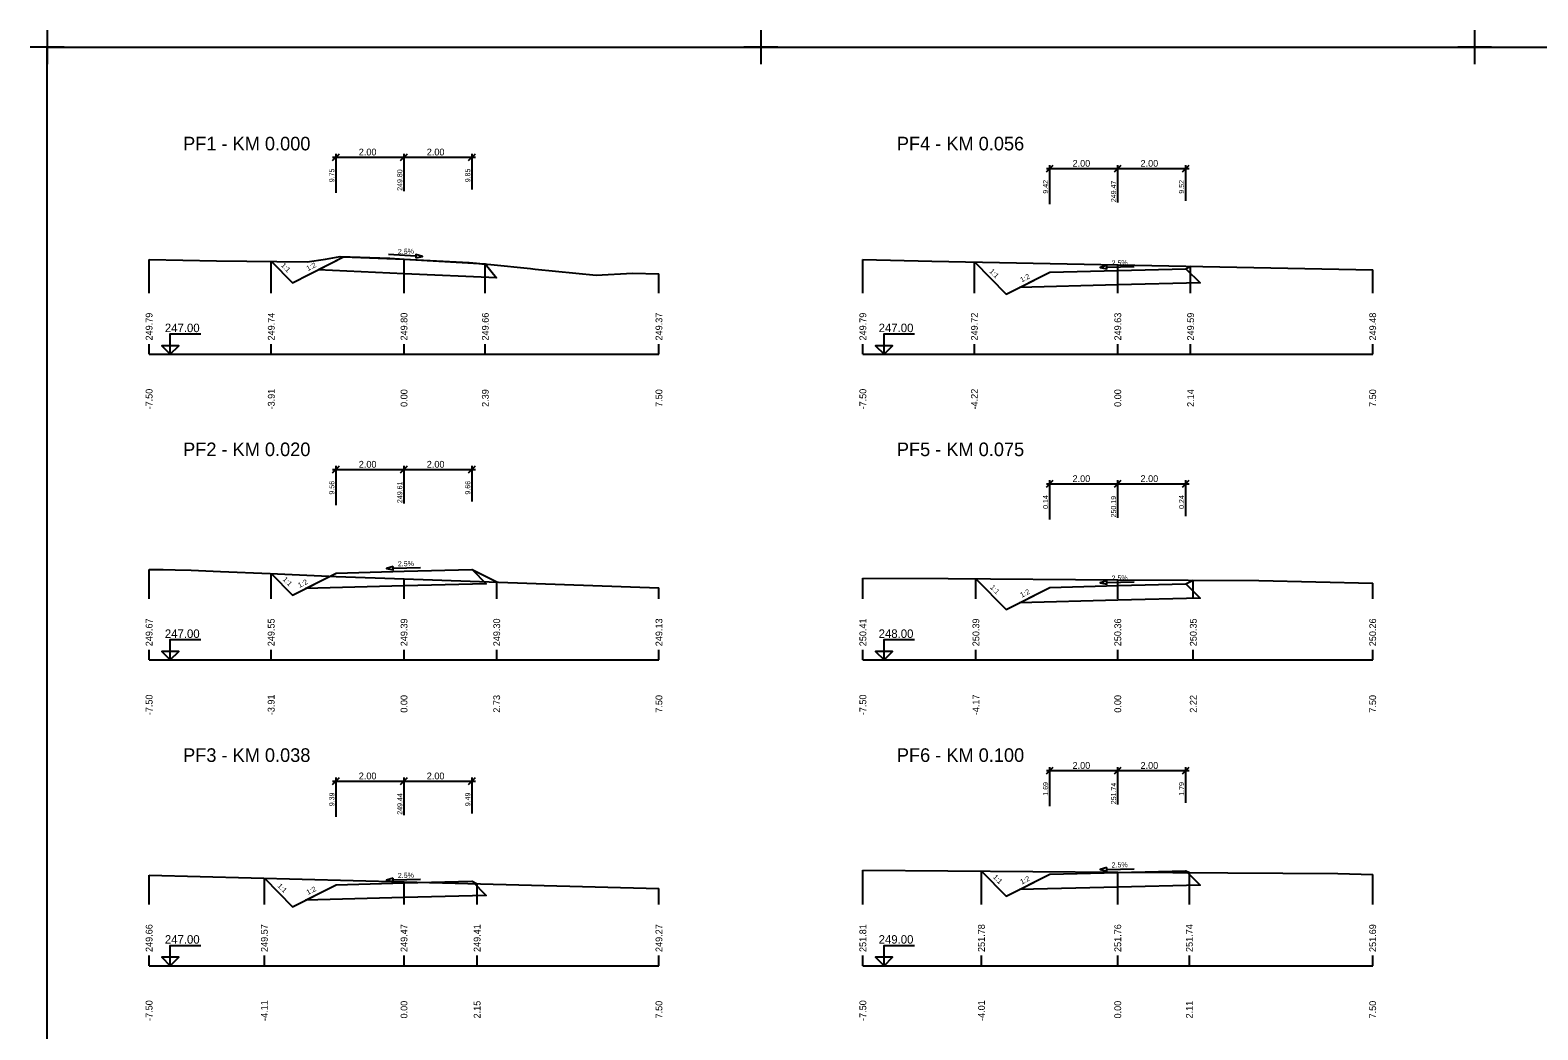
# Model space of a CAD drawing. Extents: x -5 to 1895, y -2 to 602.
# Drawn here: x -5 to 438.6, y 308.1 to 602.4 of the extents above; entities that cross this region are included whole.
import ezdxf

# ---------------------------------------------------------------- set-up
doc = ezdxf.new("R2010")
doc.units = 0
for name, color, linetype in [('KOTA', 7, 'Continuous'), ('KOTA_DELKY', 7, 'Continuous'), ('KOTA_DELKY_CONT', 7, 'Continuous'), ('NS_TELESO_VOZOVKY', 7, 'Continuous'), ('NS_V_PF', 7, 'Continuous'), ('REZY_PF_PUVODNI', 7, 'Continuous'), ('SESTAVY_REZU_PF', 7, 'Continuous'), ('SKLON', 7, 'Continuous'), ('SVK', 7, 'Continuous')]:
    doc.layers.add(name, color=color, linetype=linetype)

msp = doc.modelspace()

# ---------------------------------------------------------------- linework, layer by layer
for p, q in [((0, 602.39), (0, 592.39)), ((0, 602.39), (0, 592.39)), ((0, 602.39), (0, 592.39)), ((0, 602.39), (0, 592.39)), ((0, 602.39), (0, 592.39)), ((0, 602.39), (0, 592.39)), ((210, 602.39), (210, 592.39)), ((210, 602.39), (210, 592.39)), ((210, 602.39), (210, 592.39)), ((210, 602.39), (210, 592.39)), ((210, 602.39), (210, 592.39)), ((210, 602.39), (210, 592.39)), ((210, 602.39), (210, 592.39)), ((210, 602.39), (210, 592.39)), ((210, 602.39), (210, 592.39)), ((210, 602.39), (210, 592.39)), ((210, 602.39), (210, 592.39)), ((210, 602.39), (210, 592.39)), ((210, 602.39), (210, 592.39)), ((210, 602.39), (210, 592.39)), ((210, 602.39), (210, 592.39)), ((210, 602.39), (210, 592.39)), ((210, 602.39), (210, 592.39)), ((210, 602.39), (210, 592.39)), ((420, 602.39), (420, 592.39)), ((420, 602.39), (420, 592.39)), ((420, 602.39), (420, 592.39)), ((420, 602.39), (420, 592.39)), ((420, 602.39), (420, 592.39)), ((420, 602.39), (420, 592.39)), ((420, 602.39), (420, 592.39)), ((420, 602.39), (420, 592.39)), ((420, 602.39), (420, 592.39)), ((420, 602.39), (420, 592.39)), ((420, 602.39), (420, 592.39)), ((420, 602.39), (420, 592.39)), ((420, 602.39), (420, 592.39)), ((420, 602.39), (420, 592.39)), ((420, 602.39), (420, 592.39)), ((420, 602.39), (420, 592.39)), ((420, 602.39), (420, 592.39)), ((420, 602.39), (420, 592.39)), ((5, 597.39), (-5, 597.39)), ((5, 597.39), (-5, 597.39)), ((5, 597.39), (-5, 597.39)), ((5, 597.39), (-5, 597.39)), ((5, 597.39), (-5, 597.39)), ((5, 597.39), (-5, 597.39)), ((215, 597.39), (205, 597.39)), ((215, 597.39), (205, 597.39)), ((215, 597.39), (205, 597.39)), ((215, 597.39), (205, 597.39)), ((215, 597.39), (205, 597.39)), ((215, 597.39), (205, 597.39)), ((215, 597.39), (205, 597.39)), ((215, 597.39), (205, 597.39)), ((215, 597.39), (205, 597.39)), ((215, 597.39), (205, 597.39)), ((215, 597.39), (205, 597.39)), ((215, 597.39), (205, 597.39)), ((215, 597.39), (205, 597.39)), ((215, 597.39), (205, 597.39)), ((215, 597.39), (205, 597.39)), ((215, 597.39), (205, 597.39)), ((215, 597.39), (205, 597.39)), ((215, 597.39), (205, 597.39)), ((425, 597.39), (415, 597.39)), ((425, 597.39), (415, 597.39)), ((425, 597.39), (415, 597.39)), ((425, 597.39), (415, 597.39)), ((425, 597.39), (415, 597.39)), ((425, 597.39), (415, 597.39)), ((425, 597.39), (415, 597.39)), ((425, 597.39), (415, 597.39)), ((425, 597.39), (415, 597.39)), ((425, 597.39), (415, 597.39)), ((425, 597.39), (415, 597.39)), ((425, 597.39), (415, 597.39)), ((425, 597.39), (415, 597.39)), ((425, 597.39), (415, 597.39)), ((425, 597.39), (415, 597.39)), ((425, 597.39), (415, 597.39)), ((425, 597.39), (415, 597.39)), ((425, 597.39), (415, 597.39))]:
    msp.add_line(p, q)
msp.add_lwpolyline([(0, 597.39), (1890, 597.39), (1890, 3.39), (0, 3.39)], close=True)
at = {"layer": 'KOTA'}
for points in [[(36.22, 509.5), (33.72, 509.5), (36.22, 507), (36.22, 513), (45.22, 513)], [(246.22, 509.5), (243.72, 509.5), (246.22, 507), (246.22, 513), (255.22, 513)], [(36.22, 507), (38.72, 509.5), (36.22, 509.5)], [(246.22, 507), (248.72, 509.5), (246.22, 509.5)], [(36.22, 419.5), (33.72, 419.5), (36.22, 417), (36.22, 423), (45.22, 423)], [(246.22, 419.5), (243.72, 419.5), (246.22, 417), (246.22, 423), (255.22, 423)], [(36.22, 417), (38.72, 419.5), (36.22, 419.5)], [(246.22, 417), (248.72, 419.5), (246.22, 419.5)], [(36.22, 329.5), (33.72, 329.5), (36.22, 327), (36.22, 333), (45.22, 333)], [(246.22, 329.5), (243.72, 329.5), (246.22, 327), (246.22, 333), (255.22, 333)], [(36.22, 327), (38.72, 329.5), (36.22, 329.5)], [(246.22, 327), (248.72, 329.5), (246.22, 329.5)]]:
    msp.add_lwpolyline(points, dxfattribs=at)
at = {"layer": 'KOTA_DELKY'}
for points in [[(84, 564.01), (86, 566.01)], [(84, 565.01), (106, 565.01)], [(85, 554.51), (85, 566.01)], [(104, 564.01), (106, 566.01)], [(104, 564.01), (106, 566.01)], [(104, 565.01), (126, 565.01)], [(105, 555.01), (105, 566.01)], [(105, 555.01), (105, 566.01)], [(124, 564.01), (126, 566.01)], [(125, 555.51), (125, 566.01)], [(294, 560.68), (296, 562.68)], [(294, 561.68), (316, 561.68)], [(295, 551.18), (295, 562.68)], [(314, 560.68), (316, 562.68)], [(314, 560.68), (316, 562.68)], [(314, 561.68), (336, 561.68)], [(315, 551.68), (315, 562.68)], [(315, 551.68), (315, 562.68)], [(334, 560.68), (336, 562.68)], [(335, 552.18), (335, 562.68)], [(84, 472.1), (86, 474.1)], [(84, 473.1), (106, 473.1)], [(85, 462.6), (85, 474.1)], [(104, 472.1), (106, 474.1)], [(104, 472.1), (106, 474.1)], [(104, 473.1), (126, 473.1)], [(105, 463.1), (105, 474.1)], [(105, 463.1), (105, 474.1)], [(124, 472.1), (126, 474.1)], [(125, 463.6), (125, 474.1)], [(294, 467.88), (296, 469.88)], [(294, 468.88), (316, 468.88)], [(295, 458.38), (295, 469.88)], [(314, 467.88), (316, 469.88)], [(314, 467.88), (316, 469.88)], [(314, 468.88), (336, 468.88)], [(315, 458.88), (315, 469.88)], [(315, 458.88), (315, 469.88)], [(334, 467.88), (336, 469.88)], [(335, 459.38), (335, 469.88)], [(84, 380.36), (86, 382.36)], [(85, 370.86), (85, 382.36)], [(104, 380.36), (106, 382.36)], [(104, 380.36), (106, 382.36)], [(105, 371.36), (105, 382.36)], [(105, 371.36), (105, 382.36)], [(124, 380.36), (126, 382.36)], [(125, 371.86), (125, 382.36)], [(294, 383.45), (296, 385.45)], [(294, 384.45), (316, 384.45)], [(295, 373.95), (295, 385.45)], [(314, 383.45), (316, 385.45)], [(314, 383.45), (316, 385.45)], [(314, 384.45), (336, 384.45)], [(315, 374.45), (315, 385.45)], [(315, 374.45), (315, 385.45)], [(334, 383.45), (336, 385.45)], [(335, 374.95), (335, 385.45)], [(84, 381.36), (106, 381.36)], [(104, 381.36), (126, 381.36)]]:
    msp.add_lwpolyline(points, dxfattribs=at)
at = {"layer": 'NS_TELESO_VOZOVKY'}
for points in [[(105, 535.01), (128.89, 533.58), (128.89, 533.58), (132.21, 529.46), (105, 530.71), (79.7, 531.86), (87.2, 535.69), (87.2, 535.69), (105, 535.01)], [(315, 531.68), (335, 532.18), (335, 532.18), (339.2, 527.98), (315, 527.38), (286.05, 526.65), (295, 531.18), (295, 531.18), (315, 531.68)], [(105, 443.1), (125, 443.6), (125, 443.6), (129.2, 439.4), (105, 438.8), (76.05, 438.08), (85, 442.6), (85, 442.6), (105, 443.1)], [(315, 438.88), (335, 439.38), (335, 439.38), (339.2, 435.19), (315, 434.58), (286.05, 433.86), (295, 438.38), (295, 438.38), (315, 438.88)], [(315, 354.45), (335, 354.95), (335, 354.95), (339.2, 350.75), (315, 350.15), (286.05, 349.43), (295, 353.95), (295, 353.95), (315, 354.45)], [(105, 351.36), (125, 351.86), (125, 351.86), (129.2, 347.66), (105, 347.06), (76.05, 346.34), (85, 350.86), (85, 350.86), (105, 351.36)]]:
    msp.add_lwpolyline(points, dxfattribs=at)
at = {"layer": 'NS_V_PF'}
for points in [[(65.94, 534.35), (72.19, 528.04), (87.2, 535.69), (87.2, 535.69), (105, 535.01), (124.21, 533.97), (124.21, 533.97), (128.92, 533.55)], [(272.82, 534.17), (282.19, 524.7), (295, 531.18), (295, 531.18), (315, 531.68), (335, 532.18), (335, 532.18), (336.43, 532.89)], [(65.91, 442.46), (72.19, 436.12), (85, 442.6), (85, 442.6), (105, 443.1), (125, 443.6), (125, 443.6), (132.27, 439.96)], [(273.26, 440.93), (282.19, 431.9), (295, 438.38), (295, 438.38), (315, 438.88), (335, 439.38), (335, 439.38), (337.21, 440.49)], [(274.89, 354.84), (282.19, 347.47), (295, 353.95), (295, 353.95), (315, 354.45), (335, 354.95), (335, 354.95), (336.06, 354.42)], [(63.91, 352.75), (72.19, 344.38), (85, 350.86), (85, 350.86), (105, 351.36), (125, 351.86), (125, 351.86), (126.51, 351.11)]]:
    msp.add_lwpolyline(points, dxfattribs=at)
at = {"layer": 'REZY_PF_PUVODNI'}
for points in [[(30, 534.88), (49.84, 534.52), (76.52, 534.24), (81.87, 534.99), (86.21, 535.74), (100.87, 535.24), (105, 535.01), (124.21, 533.97), (130.52, 533.41), (142.2, 532.26), (143.63, 532.01), (161.57, 530.24), (172.23, 530.9), (180, 530.67)], [(240, 534.92), (260.27, 534.42), (315, 533.32), (390, 531.82)], [(30, 443.68), (34.16, 443.61), (37.66, 443.53), (42.36, 443.45), (50.98, 443.04), (65.65, 442.48), (85.02, 441.62), (105, 440.92), (180, 438.28)], [(240, 441.07), (265.09, 440.99), (315, 440.64), (356.49, 440.35), (390, 439.59)], [(240, 355.09), (315, 354.57), (379.76, 354.12), (390, 353.89)], [(30, 353.64), (105, 351.67), (180, 349.7)]]:
    msp.add_lwpolyline(points, dxfattribs=at)
at = {"layer": 'SESTAVY_REZU_PF'}
for points in [[(30, 507), (180, 507)], [(240, 507), (390, 507)], [(30, 417), (180, 417)], [(240, 417), (390, 417)], [(30, 327), (180, 327)], [(240, 327), (390, 327)]]:
    msp.add_lwpolyline(points, dxfattribs=at)
at = {"layer": 'SKLON'}
for points in [[(108.47, 535.84), (100.48, 536.33)], [(108.44, 535.34), (110.46, 535.72), (108.5, 536.34), (108.44, 535.34)], [(311.79, 533.1), (309.8, 532.55), (311.81, 532.1), (311.79, 533.1)], [(311.8, 532.6), (319.8, 532.8)], [(101.79, 444.52), (99.8, 443.97), (101.81, 443.52), (101.79, 444.52)], [(101.8, 444.02), (109.8, 444.22)], [(311.79, 440.3), (309.8, 439.75), (311.81, 439.3), (311.79, 440.3)], [(311.8, 439.8), (319.8, 440)], [(311.79, 355.87), (309.8, 355.32), (311.81, 354.87), (311.79, 355.87)], [(311.8, 355.37), (319.8, 355.57)], [(101.79, 352.78), (99.8, 352.23), (101.81, 351.78), (101.79, 352.78)], [(101.8, 352.28), (109.8, 352.48)]]:
    msp.add_lwpolyline(points, dxfattribs=at)
at = {"layer": 'SVK'}
for points in [[(30, 525), (30, 534.88)], [(65.94, 525), (65.94, 534.35)], [(105, 525), (105, 535.01)], [(128.92, 525), (128.92, 533.55)], [(240, 525), (240, 534.92)], [(272.82, 525), (272.82, 534.17)], [(315, 525), (315, 533.32)], [(336.43, 525), (336.43, 532.89)], [(180, 525), (180, 530.67)], [(390, 525), (390, 531.82)], [(30, 507), (30, 510)], [(65.94, 507), (65.94, 510)], [(105, 507), (105, 510)], [(128.92, 507), (128.92, 510)], [(180, 507), (180, 510)], [(240, 507), (240, 510)], [(272.82, 507), (272.82, 510)], [(315, 507), (315, 510)], [(336.43, 507), (336.43, 510)], [(390, 507), (390, 510)], [(30, 435), (30, 443.68)], [(65.91, 435), (65.91, 442.46)], [(105, 435), (105, 440.92)], [(132.27, 435), (132.27, 439.96)], [(240, 435), (240, 441.07)], [(273.26, 435), (273.26, 440.93)], [(315, 435), (315, 440.64)], [(337.21, 435), (337.21, 440.49)], [(390, 435), (390, 439.59)], [(180, 435), (180, 438.28)], [(30, 417), (30, 420)], [(65.91, 417), (65.91, 420)], [(105, 417), (105, 420)], [(132.27, 417), (132.27, 420)], [(180, 417), (180, 420)], [(240, 417), (240, 420)], [(273.26, 417), (273.26, 420)], [(315, 417), (315, 420)], [(337.21, 417), (337.21, 420)], [(390, 417), (390, 420)], [(240, 345), (240, 355.09)], [(30, 345), (30, 353.64)], [(63.91, 345), (63.91, 352.75)], [(105, 345), (105, 351.67)], [(126.51, 345), (126.51, 351.11)], [(274.89, 345), (274.89, 354.84)], [(315, 345), (315, 354.57)], [(336.06, 345), (336.06, 354.42)], [(390, 345), (390, 353.89)], [(180, 345), (180, 349.7)], [(30, 327), (30, 330)], [(63.91, 327), (63.91, 330)], [(105, 327), (105, 330)], [(126.51, 327), (126.51, 330)], [(180, 327), (180, 330)], [(240, 327), (240, 330)], [(274.89, 327), (274.89, 330)], [(315, 327), (315, 330)], [(336.06, 327), (336.06, 330)], [(390, 327), (390, 330)]]:
    msp.add_lwpolyline(points, dxfattribs=at)

# ---------------------------------------------------------------- texts
at = {"layer": 'KOTA'}
for s, p in [('247.00', (34.64, 513.5)), ('247.00', (244.64, 513.5)), ('247.00', (34.64, 423.5)), ('248.00', (244.64, 423.5)), ('247.00', (34.64, 333.5)), ('249.00', (244.64, 333.5))]:
    msp.add_text(s, height=2.5, dxfattribs=at).set_placement(p)
at = {"layer": 'KOTA_DELKY'}
for p in [(91.69, 565.51), (111.69, 565.51), (301.69, 562.18), (321.69, 562.18), (91.69, 473.6), (111.69, 473.6), (301.69, 469.38), (321.69, 469.38), (301.69, 384.95), (321.69, 384.95), (91.69, 381.86), (111.69, 381.86)]:
    msp.add_text('2.00', height=2, dxfattribs=at).set_placement(p)
at = {"layer": 'KOTA_DELKY_CONT'}
for s, p in [('9.75', (84.5, 557.6)), ('249.80', (104.5, 555.09)), ('9.85', (124.5, 557.6)), ('9.42', (294.5, 554.26)), ('249.47', (314.5, 551.75)), ('9.52', (334.5, 554.26)), ('9.56', (84.5, 465.69)), ('249.61', (104.5, 463.18)), ('9.66', (124.5, 465.69)), ('0.14', (294.5, 461.47)), ('250.19', (314.5, 458.96)), ('0.24', (334.5, 461.47)), ('9.39', (84.5, 373.95)), ('249.44', (104.5, 371.44)), ('9.49', (124.5, 373.95)), ('1.69', (294.5, 377.04)), ('251.74', (314.5, 374.53)), ('1.79', (334.5, 377.04))]:
    msp.add_text(s, height=1.5, rotation=90, dxfattribs=at).set_placement(p)
at = {"layer": 'SESTAVY_REZU_PF'}
for s, p in [('PF1 - KM 0.000', (40, 567)), ('PF4 - KM 0.056', (250, 567)), ('PF2 - KM 0.020', (40, 477)), ('PF5 - KM 0.075', (250, 477)), ('PF3 - KM 0.038', (40, 387)), ('PF6 - KM 0.100', (250, 387))]:
    msp.add_text(s, height=4, dxfattribs=at).set_placement(p)
at = {"layer": 'SKLON'}
for s, rotation, p in [('2.5%', 1.4321, (103.2, 536.47)), ('1:1', 314.7121, (68.67, 533.02)), ('1:2', 26.8233, (76.74, 531.46)), ('2.5%', 1.4321, (313.2, 533.13)), ('1:1', 314.7121, (277.11, 531.26)), ('1:2', 26.8233, (286.74, 528.12)), ('2.5%', 1.4321, (103.2, 444.55)), ('1:1', 314.7121, (69.17, 440.59)), ('1:2', 26.8233, (74.25, 438.21)), ('2.5%', 1.4321, (313.2, 440.34)), ('1:1', 314.7121, (277.33, 438.24)), ('1:2', 26.8233, (286.74, 435.32)), ('2.5%', 1.4321, (313.2, 355.9)), ('1:1', 314.7121, (67.65, 350.39)), ('2.5%', 1.4321, (103.2, 352.81)), ('1:1', 314.7121, (278.14, 352.98)), ('1:2', 26.8233, (286.74, 350.89)), ('1:2', 26.8233, (76.74, 347.8))]:
    msp.add_text(s, height=1.5, rotation=rotation, dxfattribs=at).set_placement(p)
at = {"layer": 'SVK'}
for s, p in [(' 249.79', (31, 510.3)), (' 249.74', (66.94, 510.3)), (' 249.80', (106, 510.3)), (' 249.66', (129.92, 510.3)), (' 249.37', (181, 510.3)), (' 249.79', (241, 510.3)), (' 249.72', (273.82, 510.3)), (' 249.63', (316, 510.3)), (' 249.59', (337.43, 510.3)), (' 249.48', (391, 510.3)), (' -7.50', (31, 490)), (' -3.91', (66.94, 490)), ('  0.00', (106, 490)), ('  2.39', (129.92, 490)), ('  7.50', (181, 490)), (' -7.50', (241, 490)), (' -4.22', (273.82, 490)), ('  0.00', (316, 490)), ('  2.14', (337.43, 490)), ('  7.50', (391, 490)), (' 249.67', (31, 420.3)), (' 249.55', (66.91, 420.3)), (' 249.39', (106, 420.3)), (' 249.30', (133.27, 420.3)), (' 249.13', (181, 420.3)), (' 250.41', (241, 420.3)), (' 250.39', (274.26, 420.3)), (' 250.36', (316, 420.3)), (' 250.35', (338.21, 420.3)), (' 250.26', (391, 420.3)), (' -7.50', (31, 400)), (' -3.91', (66.91, 400)), ('  0.00', (106, 400)), ('  2.73', (133.27, 400)), ('  7.50', (181, 400)), (' -7.50', (241, 400)), (' -4.17', (274.26, 400)), ('  0.00', (316, 400)), ('  2.22', (338.21, 400)), ('  7.50', (391, 400)), (' 249.66', (31, 330.3)), (' 249.57', (64.91, 330.3)), (' 249.47', (106, 330.3)), (' 249.41', (127.51, 330.3)), (' 249.27', (181, 330.3)), (' 251.81', (241, 330.3)), (' 251.78', (275.89, 330.3)), (' 251.76', (316, 330.3)), (' 251.74', (337.06, 330.3)), (' 251.69', (391, 330.3)), (' -7.50', (31, 310)), (' -4.11', (64.91, 310)), ('  0.00', (106, 310)), ('  2.15', (127.51, 310)), ('  7.50', (181, 310)), (' -7.50', (241, 310)), (' -4.01', (275.89, 310)), ('  0.00', (316, 310)), ('  2.11', (337.06, 310)), ('  7.50', (391, 310))]:
    msp.add_text(s, height=2, rotation=90, dxfattribs=at).set_placement(p)

doc.saveas('drawing.dxf')
